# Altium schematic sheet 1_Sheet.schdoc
size 426 x 302 mm; Name: A_A3; Symbol: A_A3; Device: A_A3; @Project Name: New Project_2023-10-27_14-14-08; REV: 1.0; Date: 2022-07-05; Sheet: 1/1; Draw By: zijunchen; Company: Your Company; Convert to PCB: yes; Add into BOM: yes
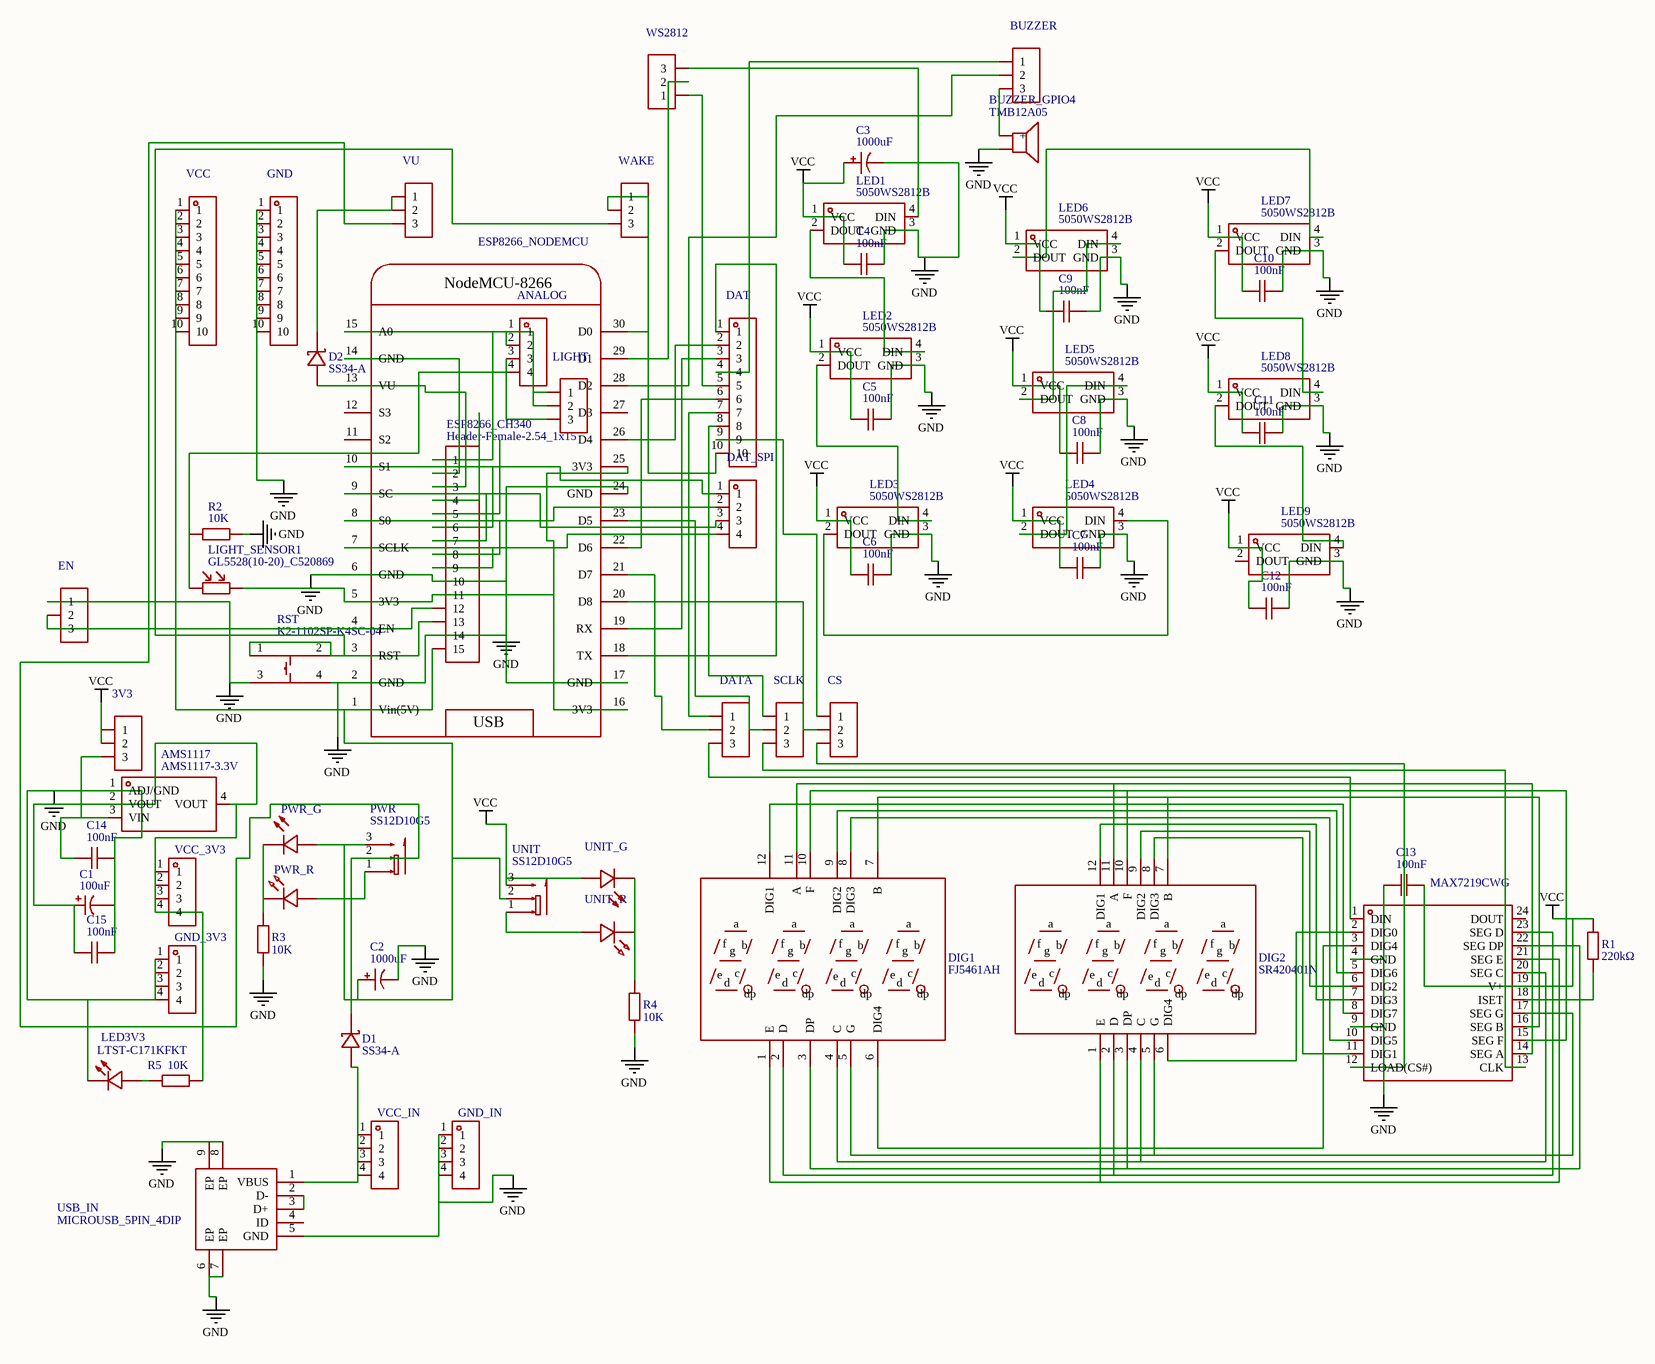
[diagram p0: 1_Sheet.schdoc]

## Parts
3V3  Header-Male-2.54_1x3  (value not drawn)
AMS1117  AMS1117-3.3V  (value not drawn)
ANALOG  PH-00316  (value not drawn)
BUZZER  Header-Male-2.54_1x3  (value not drawn)
BUZZER_GPIO4  TMB12A05  (value not drawn)
C1  100uF  (value not drawn)
C2  1000uF  (value not drawn)
C3  1000uF  (value not drawn)
C4  100nF  (value not drawn)
C5  100nF  (value not drawn)
C6  100nF  (value not drawn)
C7  100nF  (value not drawn)
C8  100nF  (value not drawn)
C9  100nF  (value not drawn)
C10  100nF  (value not drawn)
C11  100nF  (value not drawn)
C12  100nF  (value not drawn)
C13  100nF  (value not drawn)
C14  100nF  (value not drawn)
C15  100nF  (value not drawn)
CS  Header-Male-2.54_1x3  (value not drawn)
D1  SS34-A  (value not drawn)
D2  SS34-A  (value not drawn)
DAT  PZ254-1-10-Z-8.5  (value not drawn)
DAT_SPI  PH-00316  (value not drawn)
DATA  Header-Male-2.54_1x3  (value not drawn)
DIG1  FJ5461AH  (value not drawn)
DIG2  SR420401N  (value not drawn)
EN  Header-Male-2.54_1x3  (value not drawn)
ESP8266_CH340  Header-Female-2.54_1x15  (value not drawn)
ESP8266_NODEMCU  NodeMCU8266  (value not drawn)
GND  PZ254-1-10-Z-8.5  (value not drawn)
GND_3V3  Z-211-0411-0021-001  (value not drawn)
GND_IN  Z-211-0411-0021-001  (value not drawn)
LED1  5050WS2812B  (value not drawn)
LED2  5050WS2812B  (value not drawn)
LED3  5050WS2812B  (value not drawn)
LED3V3  LTST-C171KFKT  (value not drawn)
LED4  5050WS2812B  (value not drawn)
LED5  5050WS2812B  (value not drawn)
LED6  5050WS2812B  (value not drawn)
LED7  5050WS2812B  (value not drawn)
LED8  5050WS2812B  (value not drawn)
LED9  5050WS2812B  (value not drawn)
LIGHT  Header-Male-2.54_1x3  (value not drawn)
LIGHT_SENSOR1  GL5528(10-20)_C520869  (value not drawn)
MAX7219CWG  MAX7219CWG  (value not drawn)
PWR  SS12D10G5  (value not drawn)
PWR_G  LTST-C170GKT  (value not drawn)
PWR_R  HL-PSC-2012S9AC-CZ  (value not drawn)
R1  220kΩ  (value not drawn)
R2  10K  (value not drawn)
R3  10K  (value not drawn)
R4  10K  (value not drawn)
R5  10K  (value not drawn)
RST  K2-1102SP-K4SC-04  (value not drawn)
SCLK  Header-Male-2.54_1x3  (value not drawn)
UNIT  SS12D10G5  (value not drawn)
UNIT_G  LTST-C170GKT  (value not drawn)
UNIT_R  HL-PSC-2012S9AC-CZ  (value not drawn)
USB_IN  MICROUSB_5PIN_4DIP  (value not drawn)
VCC  PZ254-1-10-Z-8.5  (value not drawn)
VCC_3V3  Z-211-0411-0021-001  (value not drawn)
VCC_IN  Z-211-0411-0021-001  (value not drawn)
VU  Header-Male-2.54_1x3  (value not drawn)
WAKE  Header-Male-2.54_1x3  (value not drawn)
WS2812  Header-Male-2.54_1x3  (value not drawn)

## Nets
GND: AMS1117.1(ADJ/GND) BUZZER_GPIO4.2 C1.2 C2.2 C3.2 C4.2 C5.2 C6.2 C7.2 C8.2 C9.2 C10.2 C11.2 C12.2 C13.1 C14.2 C15.2 EN.1 ESP8266_CH340.10 ESP8266_CH340.14 ESP8266_NODEMCU.2(GND) ESP8266_NODEMCU.6(GND) ESP8266_NODEMCU.17(GND) ESP8266_NODEMCU.24(GND) GND.1 GND.2 GND.3 GND.4 GND.5 GND.6 GND.7 GND.8 GND.9 GND.10 GND_3V3.1 GND_3V3.2 GND_3V3.3 GND_3V3.4 GND_IN.1 GND_IN.2 GND_IN.3 GND_IN.4 LED1.3(GND) LED2.3(GND) LED3.3(GND) LED3V3.1(C) LED4.3(GND) LED5.3(GND) LED6.3(GND) LED7.3(GND) LED8.3(GND) LED9.3(GND) MAX7219CWG.4(GND) MAX7219CWG.9(GND) R2.2 R3.1 R4.1 RST.3 RST.4 USB_IN.5(GND) USB_IN.6(EP) USB_IN.7(EP) USB_IN.8(EP) USB_IN.9(EP)
VCC: 3V3.1 3V3.2 C3.1 C4.1 C5.1 C6.1 C7.1 C8.1 C9.1 C10.1 C11.1 C12.1 C13.2 LED1.1(VCC) LED2.1(VCC) LED3.1(VCC) LED4.1(VCC) LED5.1(VCC) LED6.1(VCC) LED7.1(VCC) LED8.1(VCC) LED9.1(VCC) MAX7219CWG.19(V+) R1.2 UNIT.3 UNIT_G.2(+)
Net3V3_3: 3V3.3 AMS1117.3(VIN) C14.1
NetAMS1117_2: AMS1117.2(VOUT) AMS1117.4(VOUT) C1.1 C15.1 R5.1 VCC_3V3.1 VCC_3V3.2 VCC_3V3.3 VCC_3V3.4
NetANALOG_1: ANALOG.1 ANALOG.2 ESP8266_CH340.1 ESP8266_NODEMCU.15(A0) LIGHT.1 LIGHT.2
NetANALOG_3: ANALOG.3 ANALOG.4 LIGHT.3 LIGHT_SENSOR1.1 R2.1
NetBUZZER_1: BUZZER.1 DAT.4
NetBUZZER_2: BUZZER.2 ESP8266_NODEMCU.28(D2)
NetBUZZER_3: BUZZER.3 BUZZER_GPIO4.1(+)
NetC2_1: C2.1 ESP8266_CH340.15 ESP8266_NODEMCU.1(Vin(5V)) PWR.3 PWR_G.2(+) UNIT.2 VCC.1 VCC.2 VCC.3 VCC.4 VCC.5 VCC.6 VCC.7 VCC.8 VCC.9 VCC.10
NetCS_1: CS.1 DAT.9
NetCS_2: CS.2 ESP8266_NODEMCU.20(D8)
NetCS_3: CS.3 MAX7219CWG.12(LOAD(CS#))
NetD1_1: D1.1(C) PWR.2 VU.3
NetD1_2: D1.2(A) USB_IN.1(VBUS) VCC_IN.1 VCC_IN.2 VCC_IN.3 VCC_IN.4
NetD2_1: D2.1(C) VU.1 VU.2
NetD2_2: D2.2(A) ESP8266_CH340.3 ESP8266_NODEMCU.13(VU)
NetDAT_1: DAT.1 ESP8266_NODEMCU.18(TX)
NetDAT_2: DAT.2 ESP8266_NODEMCU.26(D4)
NetDAT_3: DAT.3 ESP8266_NODEMCU.19(RX)
NetDAT_5: DAT.5 WS2812.1
NetDAT_6: DAT.6 ESP8266_NODEMCU.22(D6)
NetDAT_7: DAT.7 DATA.1
NetDAT_8: DAT.8 SCLK.1
NetDAT_10: DAT.10 ESP8266_NODEMCU.30(D0) WAKE.1 WAKE.2
NetDAT_SPI_1: DAT_SPI.1 ESP8266_CH340.6 ESP8266_NODEMCU.10(S1)
NetDAT_SPI_2: DAT_SPI.2 ESP8266_CH340.8 ESP8266_NODEMCU.8(S0)
NetDAT_SPI_3: DAT_SPI.3 ESP8266_CH340.7 ESP8266_NODEMCU.9(SC)
NetDAT_SPI_4: DAT_SPI.4 ESP8266_CH340.9 ESP8266_NODEMCU.7(SCLK)
NetDATA_2: DATA.2 ESP8266_NODEMCU.21(D7)
NetDATA_3: DATA.3 MAX7219CWG.1(DIN)
NetDIG1_1: DIG1.1(E) DIG2.1(E) MAX7219CWG.21(SEG_E)
NetDIG1_2: DIG1.2(D) DIG2.2(D) MAX7219CWG.23(SEG_D)
NetDIG1_3: DIG1.3(DP) DIG2.3(DP) MAX7219CWG.22(SEG_DP)
NetDIG1_4: DIG1.4(C) DIG2.4(C) MAX7219CWG.20(SEG_C)
NetDIG1_5: DIG1.5(G) DIG2.5(G) MAX7219CWG.17(SEG_G)
NetDIG1_6: DIG1.6(DIG4) MAX7219CWG.3(DIG4)
NetDIG1_7: DIG1.7(B) DIG2.7(B) MAX7219CWG.16(SEG_B)
NetDIG1_8: DIG1.8(DIG3) MAX7219CWG.10(DIG5)
NetDIG1_9: DIG1.9(DIG2) MAX7219CWG.5(DIG6)
NetDIG1_10: DIG1.10(F) DIG2.10(F) MAX7219CWG.15(SEG_F)
NetDIG1_11: DIG1.11(A) DIG2.11(A) MAX7219CWG.14(SEG_A)
NetDIG1_12: DIG1.12(DIG1) MAX7219CWG.8(DIG7)
NetDIG2_6: DIG2.6(DIG4) MAX7219CWG.2(DIG0)
NetDIG2_8: DIG2.8(DIG3) MAX7219CWG.11(DIG1)
NetDIG2_9: DIG2.9(DIG2) MAX7219CWG.6(DIG2)
NetDIG2_12: DIG2.12(DIG1) MAX7219CWG.7(DIG3)
NetEN_2: EN.2 EN.3 ESP8266_CH340.12 ESP8266_NODEMCU.4(EN)
NetESP8266_CH340_2: ESP8266_CH340.2 ESP8266_NODEMCU.14(GND)
NetESP8266_CH340_11: ESP8266_CH340.11 ESP8266_NODEMCU.5(3V3) ESP8266_NODEMCU.16(3V3) ESP8266_NODEMCU.25(3V3) LIGHT_SENSOR1.2
NetESP8266_CH340_13: ESP8266_CH340.13 ESP8266_NODEMCU.3(RST) RST.1 RST.2 WAKE.3
NetESP8266_NODEMCU_23: ESP8266_NODEMCU.23(D5) SCLK.2
NetESP8266_NODEMCU_29: ESP8266_NODEMCU.29(D1) WS2812.2
NetLED1_2: LED1.2(DOUT) LED2.4(DIN)
NetLED1_4: LED1.4(DIN) WS2812.3
NetLED2_2: LED2.2(DOUT) LED3.4(DIN)
NetLED3_2: LED3.2(DOUT) LED4.4(DIN)
NetLED3V3_2: LED3V3.2(A) R5.2
NetLED4_2: LED4.2(DOUT) LED5.4(DIN)
NetLED5_2: LED5.2(DOUT) LED6.4(DIN)
NetLED6_2: LED6.2(DOUT) LED7.4(DIN)
NetLED7_2: LED7.2(DOUT) LED8.4(DIN)
NetLED8_2: LED8.2(DOUT) LED9.4(DIN)
NetMAX7219CWG_13: MAX7219CWG.13(CLK) SCLK.3
NetMAX7219CWG_18: MAX7219CWG.18(ISET) R1.1
NetPWR_1: PWR.1 PWR_R.2(+)
NetPWR_G_1: PWR_G.1(-) PWR_R.1(-) R3.2
NetR4_2: R4.2 UNIT_G.1(-) UNIT_R.1(-)
NetUNIT_1: UNIT.1 UNIT_R.2(+)
NetUSB_IN_2: USB_IN.2(D-) USB_IN.3(D+)

Not connected (* = marked no-connect by the designer): ESP8266_CH340 4 5; ESP8266_NODEMCU 11(S2) 12(S3) 27(D3); LED9 2(DOUT); MAX7219CWG 24(DOUT); USB_IN 4(ID)

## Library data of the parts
3V3 BUZZER CS DATA EN LIGHT SCLK VU WAKE WS2812 = Header-Male-2.54_1x3: Manufacturer: BOOMELE; Manufacturer Part: Header2.54mm 1*3P; Convert to PCB: yes; Origin Footprint: HDR-TH_3P-P2.54-V-M-1
AMS1117 = AMS1117-3.3V: Manufacturer: WPMtek(维攀微); Convert to PCB: yes; Origin Footprint: SOT-223-4_L6.5-W3.5-P2.30-LS7.0-BR
ANALOG DAT_SPI = PH-00316: Manufacturer: Liansheng(连盛); Convert to PCB: yes; Origin Footprint: HDR-TH_4P-P2.54-V-M
BUZZER_GPIO4 = TMB12A05: Manufacturer: HNDZ; Frequency: 2300Hz; Convert to PCB: yes; Origin Footprint: BUZ-TH_BD12.0-P7.60-D0.6-FD
C1 = 100uF: Manufacturer: HRK(鸿瑞凯电子); Manufacturer Part: 35V100uF CD288; Convert to PCB: yes; Origin Footprint: CAP-TH_BD6.0-P2.50-D0.5-FD
C2 C3 = 1000uF: Manufacturer: ValuePro; Manufacturer Part: 1000uF 16Vblack gold 8*20; Convert to PCB: yes; Origin Footprint: CAP-TH_BD8.0-P3.50-D0.6-FD
C4-C15 = 100nF: Manufacturer: CCTC; Manufacturer Part: TCC0805X7R104M500DT; Convert to PCB: yes; Origin Footprint: C0805
D1 D2 = SS34-A: Manufacturer: Formosa Microsemi; Convert to PCB: yes; Origin Footprint: SMA_L4.3-W2.6-LS5.2-RD
DAT GND VCC = PZ254-1-10-Z-8.5: Manufacturer: HCTL(华灿天禄); Convert to PCB: yes; Origin Footprint: HDR-TH_10P-P2.54-V-M
DIG1 = FJ5461AH: Manufacturer: ReliaPro; Manufacturer Part: FJ5461AH 橙红; Convert to PCB: yes; Origin Footprint: LED-SEG-TH_12P-L50.3-W19.0-P2.54-S15.24-BL
DIG2 = SR420401N: Manufacturer: ARKLED; Convert to PCB: yes; Origin Footprint: LED-SEG-TH_12P-L40.5-W16.0-P2.54-S12.70-BL
ESP8266_CH340 = Header-Female-2.54_1x15: Manufacturer: Ckmtw; Manufacturer Part: 220S-1*15P H=8.5MM Ytype Gold-plated; Convert to PCB: yes; Origin Footprint: HDR-TH_15P-P2.54-V-F-1
ESP8266_NODEMCU = NodeMCU8266: Convert to PCB: yes
GND_3V3 GND_IN VCC_3V3 VCC_IN = Z-211-0411-0021-001: Manufacturer: ZHENGLING; Convert to PCB: yes; Origin Footprint: HDR-TH_4P-P2.54-V-M
LED1-LED9 = 5050WS2812B: Manufacturer: null; Convert to PCB: yes; Origin Footprint: LED-SMD_5050WS2812B
LED3V3 = LTST-C171KFKT: Manufacturer: Lite-On; Convert to PCB: yes; Origin Footprint: LED0805-RD_ORANGE
LIGHT_SENSOR1 = GL5528(10-20)_C520869: Manufacturer: JCHL(Shenzhen Jing Chuang He Li Tech); Convert to PCB: yes; Origin Footprint: RES-TH_L5.1-W4.3-P3.40-D0.5
MAX7219CWG = MAX7219CWG: Manufacturer: MAXIM; Convert to PCB: yes; Origin Footprint: SOIC-24_L15.4-W7.5-P1.27-LS10.3-BL
PWR UNIT = SS12D10G5: Convert to PCB: yes
PWR_G UNIT_G = LTST-C170GKT: Manufacturer: Lite-On; Convert to PCB: yes; Origin Footprint: LED0805-RD_GREEN
PWR_R UNIT_R = HL-PSC-2012S9AC-CZ: Manufacturer: HONGLITRONIC(Hongli Zhihui (HONGLITRONIC)); Convert to PCB: yes; Origin Footprint: LED0805-RD_RED
R1 = 220kΩ: Manufacturer: EVER OHMS; Manufacturer Part: CR2010J220KE04; Resistance: 220K; Convert to PCB: yes; Origin Footprint: R2010
R2 = 10K: Manufacturer: null; Manufacturer Part: 0R005/1%3W/R2512; Convert to PCB: yes; Origin Footprint: R2512
R3-R5 = 10K: Manufacturer: YAGEO; Manufacturer Part: RT1206BRD0710KL; Resistance: 10kΩ; Convert to PCB: yes; Origin Footprint: R1206
RST = K2-1102SP-K4SC-04: Manufacturer: HRO; Convert to PCB: yes; Origin Footprint: KEY-SMD_4P-L6.0-W6.0-P4.50-LS9.5-BL
USB_IN = MICROUSB_5PIN_4DIP: Manufacturer: null; Convert to PCB: yes; Origin Footprint: MICRO-USB-SMD_U254-051N-4BH806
